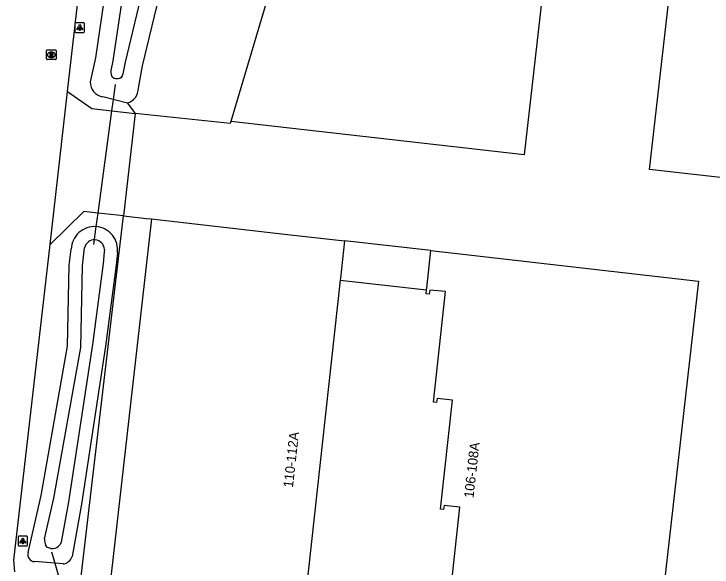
# Model space of a CAD drawing. Extents: x 161389 to 162585, y 388479 to 389761.
# Drawn here: x 162340.7 to 162413.1, y 388689.8 to 388747.2 of the extents above; entities that cross this region are included whole.
import ezdxf

# ---------------------------------------------------------------- set-up
doc = ezdxf.new("R2010")
doc.units = 0
for name, color, linetype in [('IMGEO_Berm_groen', 7, 'Continuous'), ('IMGEO_Duiker', 7, 'Continuous'), ('IMGEO_Groenvoorziening', 7, 'Continuous'), ('IMGEO_Lichtpunt', 7, 'Continuous'), ('IMGEO_Pand', 7, 'Continuous'), ('IMGEO_Pand_nummerreeks', 7, 'Continuous'), ('IMGEO_Pand_overbouw', 7, 'Continuous'), ('IMGEO_Rijbaan_lokaal_gesloten', 7, 'Continuous'), ('IMGEO_Rioolput', 7, 'Continuous'), ('IMGEO_Voetpad_open', 7, 'Continuous'), ('IMGEO_Waterloop', 7, 'Continuous')]:
    doc.layers.add(name, color=color, linetype=linetype)

msp = doc.modelspace()

# ---------------------------------------------------------------- linework, layer by layer
at = {"layer": 'IMGEO_Berm_groen'}
for points in [[(162353.858, 388784.024), (162350.241, 388750), (162349.171, 388742.638), (162348.615, 388740.14)], [(162349.912, 388738.601), (162352.485, 388737.95)], [(162353.271, 388736.845), (162353.252, 388736.953), (162352.485, 388737.95)], [(162346.834, 388681.784), (162352.07, 388726.225)], [(162342.165, 388691.342), (162343.516, 388697.245), (162346.278, 388712.718), (162346.445, 388721.142), (162346.654, 388722.778)], [(162351.437, 388722.404), (162351.311, 388721.134), (162350.189, 388712.718), (162347.727, 388696.352), (162346.734, 388690.917)], [(162345.796, 388690.134), (162342.829, 388690.376)]]:
    msp.add_lwpolyline(points, dxfattribs=at)
for centre, radius, start, end in [((162350.129, 388740.1), 1.515, 178.49776, 261.7476), ((162349.056, 388722.723), 2.402, 85.69963, 178.69515), ((162349.055, 388722.723), 2.403, 352.3746, 85.68748), ((162342.896, 388691.133), 0.76, 164.02945, 264.97753), ((162345.638, 388691.277), 1.154, 277.88039, 341.82682)]:
    msp.add_arc(centre, radius, start, end, dxfattribs=at)
at = {"layer": 'IMGEO_Duiker'}
for points in [[(162348.984, 388723.268), (162349.236, 388725.119), (162349.427, 388726.526), (162350.868, 388737.124), (162351.03, 388738.318), (162351.242, 388739.878)], [(162351.955, 388666.009), (162351.521, 388667.511), (162350.951, 388669.489), (162350.891, 388669.698), (162348.811, 388676.9), (162348.434, 388678.207), (162347.583, 388681.157), (162346.998, 388683.179), (162344.972, 388690.201), (162344.637, 388691.361)]]:
    msp.add_lwpolyline(points, dxfattribs=at)
at = {"layer": 'IMGEO_Groenvoorziening'}
for points in [[(162353.626, 388739.483), (162354.058, 388741.791), (162356.029, 388750), (162363.459, 388781.811), (162364.13, 388783.523), (162364.471, 388787.302)], [(162363.204, 388736.022), (162363.147, 388735.83), (162353.271, 388736.845)], [(162352.07, 388726.225), (162354.453, 388725.972), (162354.964, 388725.918)]]:
    msp.add_lwpolyline(points, dxfattribs=at)
msp.add_arc((162351.999, 388739.503), 1.627, 287.37928, 359.30067, dxfattribs=at)
at = {"layer": 'IMGEO_Lichtpunt'}
for p, q in [((162347.037, 388746.173), (162347.037, 388745.366)), ((162347.037, 388746.173), (162347.037, 388745.366)), ((162347.939, 388746.268), (162347.131, 388746.268)), ((162347.939, 388746.268), (162347.131, 388746.268)), ((162348.033, 388745.366), (162348.033, 388746.173)), ((162348.033, 388745.366), (162348.033, 388746.173)), ((162347.131, 388745.272), (162347.939, 388745.272)), ((162347.131, 388745.272), (162347.939, 388745.272)), ((162341.129, 388692.924), (162341.129, 388692.117)), ((162341.129, 388692.924), (162341.129, 388692.117)), ((162342.031, 388693.019), (162341.223, 388693.019)), ((162342.031, 388693.019), (162341.223, 388693.019)), ((162342.125, 388692.117), (162342.125, 388692.924)), ((162342.125, 388692.117), (162342.125, 388692.924)), ((162341.223, 388692.023), (162342.031, 388692.023)), ((162341.223, 388692.023), (162342.031, 388692.023))]:
    msp.add_line(p, q, dxfattribs=at)
for points in [[(162347.411, 388745.837), (162347.45, 388745.809), (162347.262, 388745.547), (162347.224, 388745.574), (162347.411, 388745.837)], [(162347.513, 388745.789), (162347.56, 388745.789), (162347.56, 388745.467), (162347.513, 388745.467), (162347.513, 388745.789)], [(162347.623, 388745.809), (162347.661, 388745.836), (162347.848, 388745.574), (162347.809, 388745.546), (162347.623, 388745.809)], [(162341.503, 388692.588), (162341.542, 388692.56), (162341.354, 388692.298), (162341.316, 388692.325), (162341.503, 388692.588)], [(162341.605, 388692.54), (162341.652, 388692.54), (162341.652, 388692.218), (162341.605, 388692.218), (162341.605, 388692.54)], [(162341.715, 388692.56), (162341.753, 388692.587), (162341.94, 388692.325), (162341.901, 388692.297), (162341.715, 388692.56)]]:
    msp.add_lwpolyline(points, dxfattribs=at)
for centre in [(162347.536, 388745.971), (162341.628, 388692.722)]:
    msp.add_circle(centre, 0.0994, dxfattribs=at)
for centre, start, end in [((162347.131, 388746.173), 90, 180), ((162347.131, 388746.173), 90, 180), ((162347.939, 388746.173), 0, 90), ((162347.939, 388746.173), 0, 90), ((162347.131, 388745.366), 180, 270), ((162347.131, 388745.366), 180, 270), ((162347.939, 388745.366), 270, 0), ((162347.939, 388745.366), 270, 360), ((162341.223, 388692.924), 90, 180), ((162341.223, 388692.924), 90, 180), ((162342.031, 388692.924), 0, 90), ((162342.031, 388692.924), 0, 90), ((162341.223, 388692.117), 180, 270), ((162341.223, 388692.117), 180, 270), ((162342.031, 388692.117), 270, 0), ((162342.031, 388692.117), 270, 360)]:
    msp.add_arc(centre, 0.0946, start, end, dxfattribs=at)
at = {"layer": 'IMGEO_Pand'}
for points in [[(162391.318, 388788.343), (162371.926, 388790.534), (162364.027, 388763.89), (162370.877, 388761.846), (162363.204, 388736.022)], [(162391.318, 388788.343), (162391.311, 388787.935), (162390.162, 388788.053), (162389.444, 388781.366), (162399.06, 388780.298), (162393.628, 388732.565), (162363.204, 388736.022)], [(162435.751, 388727.776), (162406.633, 388731.063), (162412.095, 388778.923)], [(162354.964, 388725.918), (162350.604, 388687.571), (162350.144, 388683.53), (162352.517, 388682.207), (162355.1, 388681.561), (162359.186, 388681.088)], [(162354.964, 388725.918), (162368.787, 388724.34), (162374.998, 388723.653), (162374.571, 388719.767), (162374.551, 388719.584), (162370.948, 388686.812), (162370.179, 388679.814)], [(162386.947, 388677.951), (162387.452, 388682.311), (162385.802, 388682.494), (162385.755, 388682.067), (162385.427, 388682.103), (162385.766, 388685.174), (162386.965, 388696.018), (162385.325, 388696.199), (162385.279, 388695.782), (162384.951, 388695.818), (162386.201, 388707.129), (162384.591, 388707.307), (162384.544, 388706.88), (162384.216, 388706.916), (162385.484, 388718.406), (162383.83, 388718.549), (162383.781, 388718.121), (162383.453, 388718.159), (162383.498, 388718.557), (162383.521, 388718.755), (162383.967, 388722.64), (162411.707, 388719.457), (162406.76, 388675.873)]]:
    msp.add_lwpolyline(points, dxfattribs=at)
at = {"layer": 'IMGEO_Pand_overbouw'}
msp.add_lwpolyline([(162383.967, 388722.64), (162374.998, 388723.653), (162374.571, 388719.767), (162374.551, 388719.584), (162383.498, 388718.557), (162383.521, 388718.755)], close=True, dxfattribs=at)
at = {"layer": 'IMGEO_Rijbaan_lokaal_gesloten'}
for points in [[(162346.266, 388739.136), (162347.508, 388750), (162351.507, 388784.973)], [(162344.45, 388723.253), (162346.266, 388739.136)], [(162340.809, 388689.333), (162340.708, 388690.523), (162344.45, 388723.253)]]:
    msp.add_lwpolyline(points, dxfattribs=at)
at = {"layer": 'IMGEO_Rioolput'}
for p, q in [((162344.085, 388742.523), (162344.085, 388743.375)), ((162344.16, 388743.449), (162345.012, 388743.449)), ((162344.573, 388743.229), (162344.598, 388743.229)), ((162345.086, 388743.375), (162345.086, 388742.523)), ((162344.596, 388742.669), (162344.571, 388742.669)), ((162345.012, 388742.449), (162344.16, 388742.449))]:
    msp.add_line(p, q, dxfattribs=at)
for points in [[(162344.085, 388742.523), (162344.085, 388743.375)], [(162344.16, 388743.449), (162345.012, 388743.449)], [(162345.086, 388743.375), (162345.086, 388742.523)], [(162344.674, 388743.147), (162344.422, 388743.149), (162344.422, 388742.749)], [(162344.422, 388742.749), (162344.546, 388742.749), (162344.546, 388742.911), (162344.557, 388742.911)], [(162344.6, 388743.068), (162344.546, 388743.068), (162344.546, 388742.987)], [(162344.546, 388742.987), (162344.598, 388742.987)], [(162344.604, 388742.882), (162344.675, 388742.749), (162344.815, 388742.749), (162344.75, 388742.875)], [(162345.012, 388742.449), (162344.16, 388742.449)]]:
    msp.add_lwpolyline(points, dxfattribs=at)
for centre, radius, start, end in [((162344.162, 388743.373), 0.0765, 91.55205, 178.44795), ((162344.162, 388743.373), 0.0765, 91.55205, 178.44795), ((162345.01, 388743.373), 0.0765, 1.55205, 88.44795), ((162345.01, 388743.373), 0.0765, 1.55205, 88.44795), ((162344.162, 388742.525), 0.0765, 181.55205, 268.44795), ((162344.162, 388742.525), 0.0765, 181.55205, 268.44795), ((162344.556, 388742.858), 0.0533, 26.02933, 88.69889), ((162344.582, 388743.176), 0.19, 274.7715, 282.96867), ((162344.606, 388742.972), 0.0964, 77.00612, 93.18647), ((162344.62, 388743.029), 0.0378, 276.66336, 79.67722), ((162344.673, 388743.037), 0.109, 350.36119, 89.41601), ((162344.671, 388743.037), 0.112, 277.58423, 350.98172), ((162344.655, 388742.822), 0.108, 29.51342, 73.79051), ((162345.01, 388742.525), 0.0765, 271.55205, 358.44795), ((162345.01, 388742.525), 0.0765, 271.55205, 358.44795)]:
    msp.add_arc(centre, radius, start, end, dxfattribs=at)
for centre, major_axis, ratio, start_param, end_param in [((162344.572, 388742.949), (-0.387, 0.002), 0.722429, 4.712389, 7.853982), ((162344.597, 388742.949), (-0.39, 0.002), 0.717154, 1.570796, 4.712389)]:
    msp.add_ellipse(centre, major_axis=major_axis, ratio=ratio, start_param=start_param, end_param=end_param, dxfattribs=at)
at = {"layer": 'IMGEO_Voetpad_open'}
for points in [[(162346.266, 388739.136), (162348.797, 388737.364), (162350.868, 388737.124), (162353.271, 388736.845)], [(162353.271, 388736.845), (162352.07, 388726.225)], [(162352.07, 388726.225), (162349.427, 388726.526), (162347.961, 388726.693), (162344.45, 388723.253)]]:
    msp.add_lwpolyline(points, dxfattribs=at)
at = {"layer": 'IMGEO_Waterloop'}
for points in [[(162362.475, 388785.925), (162362.297, 388783.956), (162361.674, 388782.366), (162354.215, 388750.43), (162352.234, 388742.18), (162352.006, 388740.959), (162351.919, 388740.769), (162351.816, 388740.604), (162351.686, 388740.494), (162351.501, 388740.445), (162351.257, 388740.46), (162351.103, 388740.498), (162350.936, 388740.601), (162350.848, 388740.757), (162350.82, 388740.858), (162350.79, 388741.139), (162350.789, 388741.329), (162351.006, 388742.301), (162352.091, 388749.767), (162355.708, 388783.794)], [(162343.884, 388692.74), (162344.853, 388696.973), (162347.639, 388712.584), (162347.807, 388721.042), (162348.039, 388722.914)], [(162350.089, 388722.754), (162350.077, 388722.507), (162349.956, 388721.291), (162348.839, 388712.91), (162346.382, 388696.576), (162345.618, 388692.398), (162345.484, 388692.171), (162345.334, 388691.97)], [(162344.548, 388691.742), (162344.201, 388691.847), (162343.985, 388692.09)]]:
    msp.add_lwpolyline(points, dxfattribs=at)
for centre, radius, start, end in [((162349.055, 388722.723), 1.034, 1.71854, 169.35582), ((162345.349, 388692.635), 1.469, 175.89666, 201.76784), ((162344.723, 388692.607), 0.882, 258.5448, 313.80759)]:
    msp.add_arc(centre, radius, start, end, dxfattribs=at)

# ---------------------------------------------------------------- texts
at = {"layer": 'IMGEO_Pand_nummerreeks'}
for s, rotation, p in [('110-112A', 83.72632, (162369.645, 388698.016)), ('106-108A', 83.69195, (162388.375, 388696.939))]:
    msp.add_text(s, height=1, rotation=rotation, dxfattribs=at).set_placement(p)

doc.saveas('drawing.dxf')
